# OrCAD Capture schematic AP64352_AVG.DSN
size D; title: 3.8V TO 40V INPUT, 3.5A LOW IQ SYNCHRONOUS BUCK; rev: 1.0; note: DS41978 Rev. 5 - 2
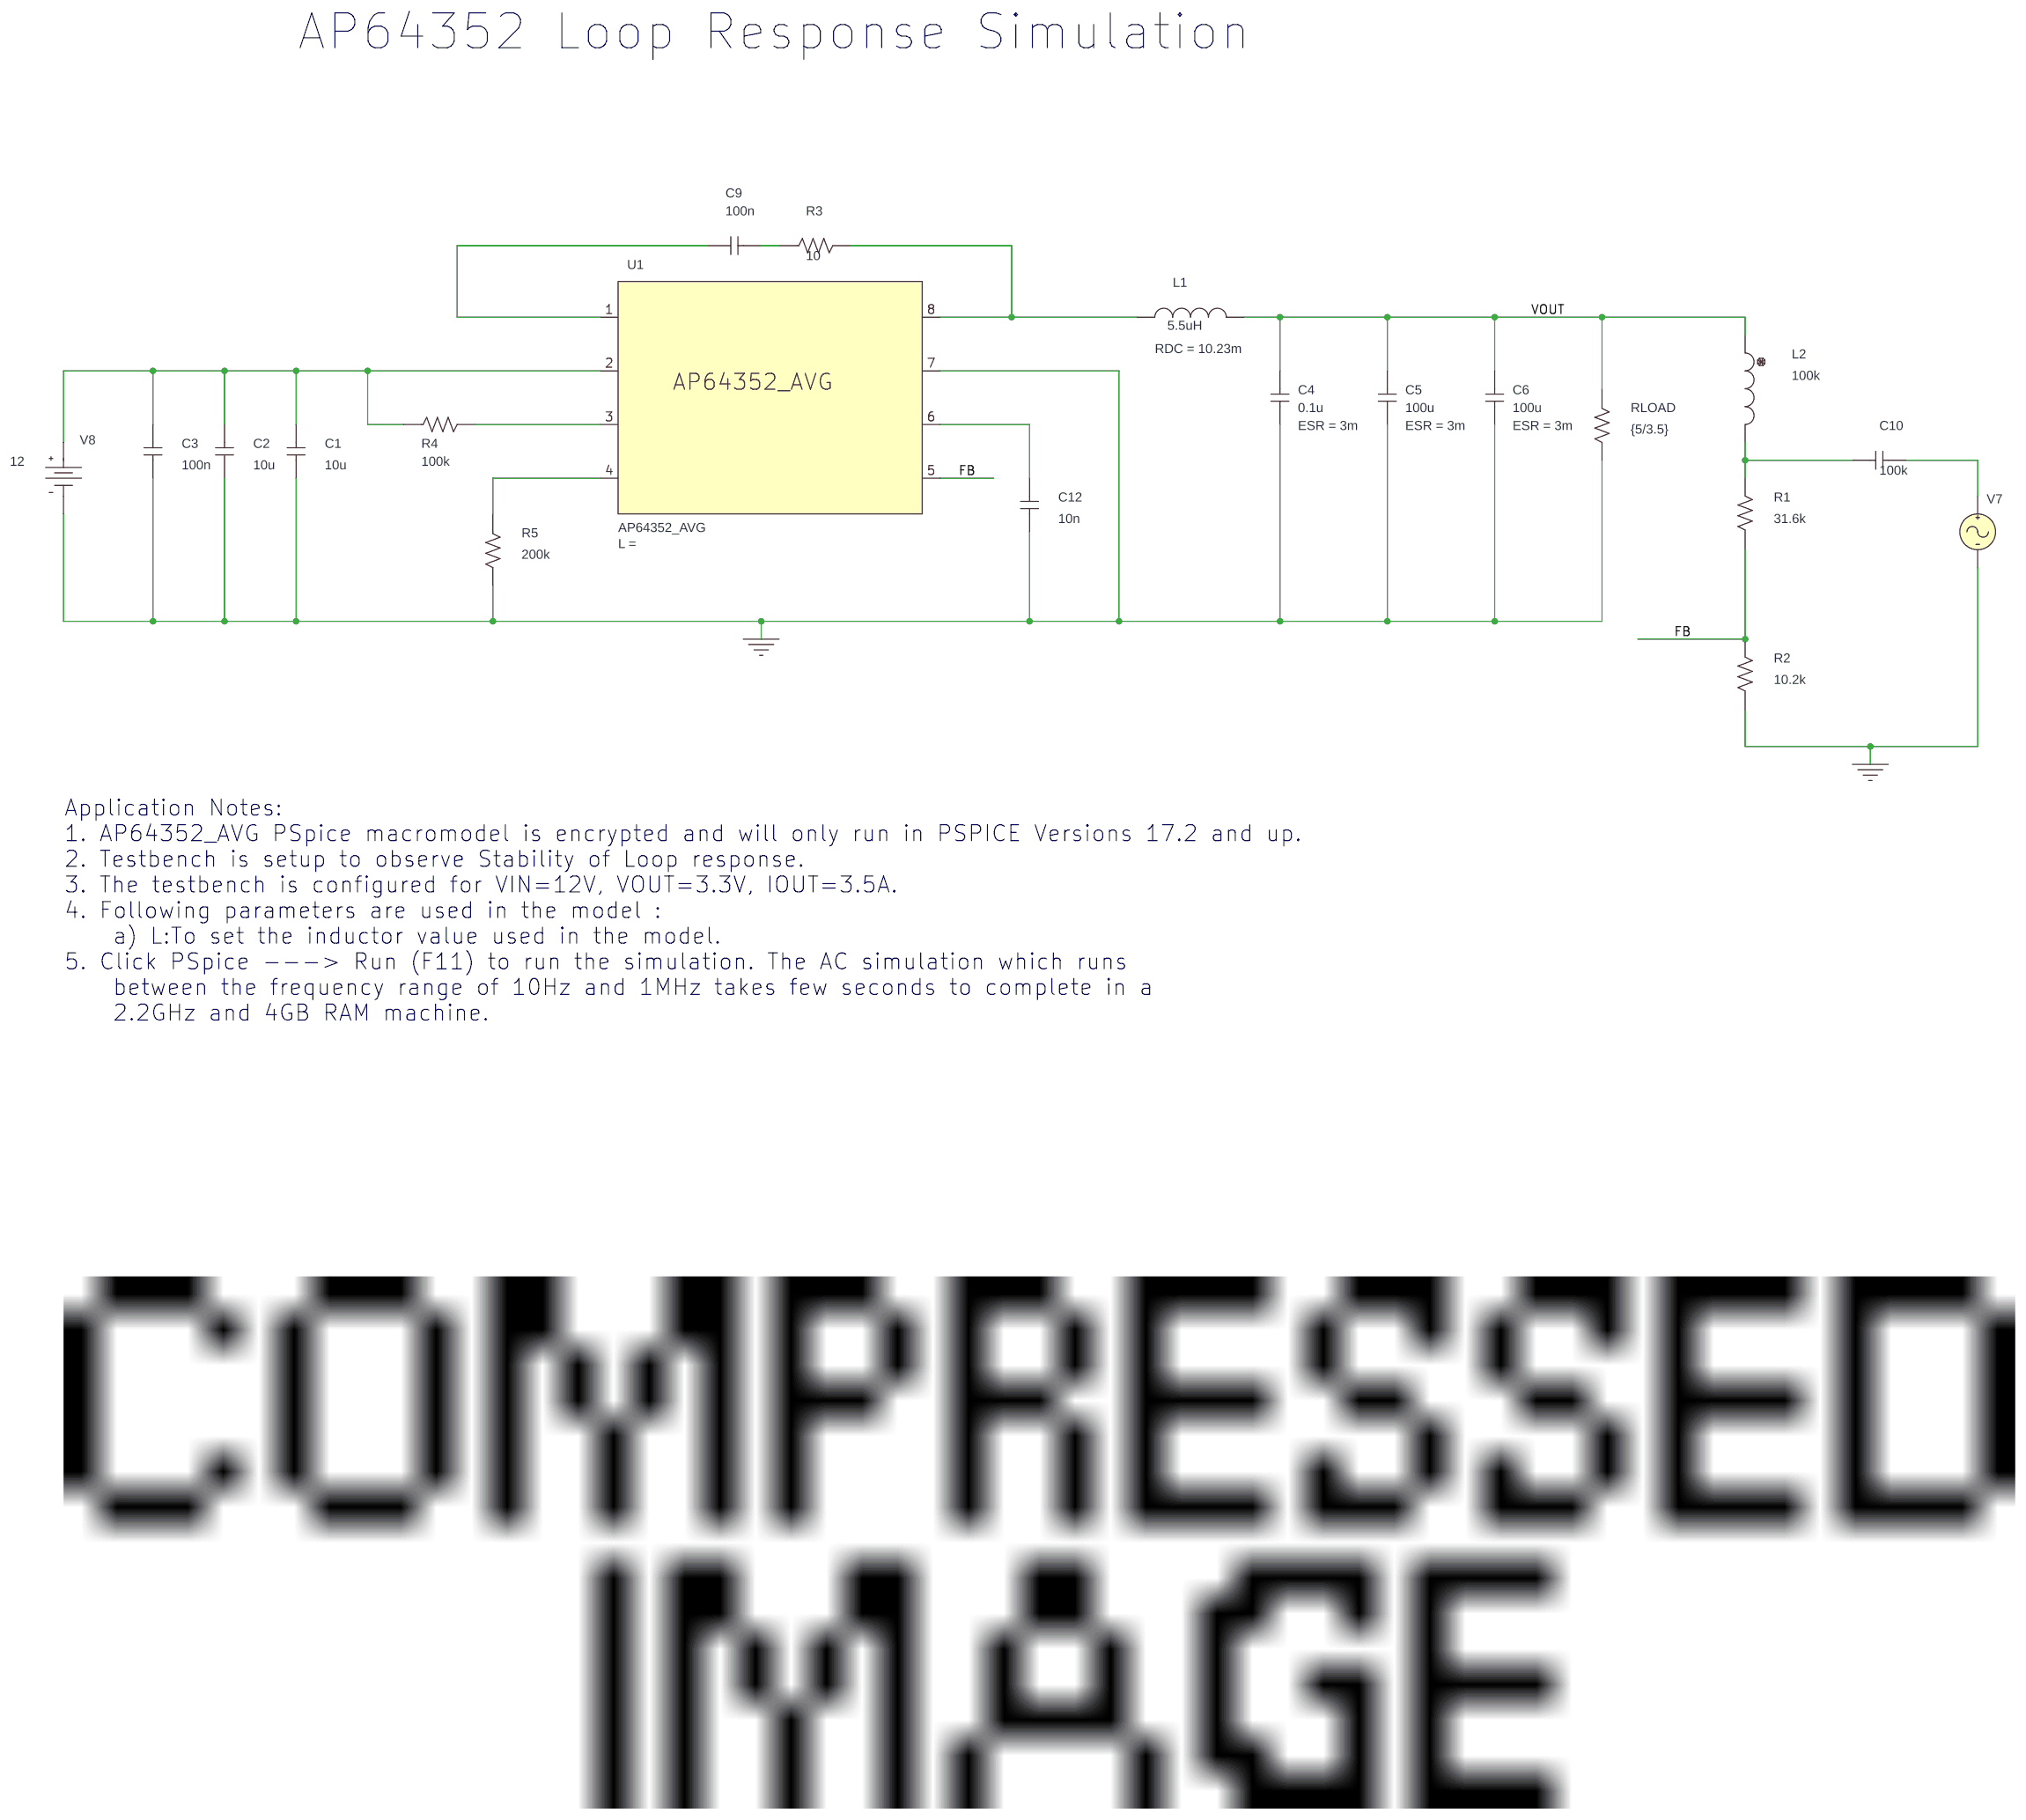
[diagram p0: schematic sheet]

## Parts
C1  10u  [cap196]
C2  10u  [cap196]
C3  100n  [cap196]
C4  0.1u  [RAD/CK05]
C5  100u  [RAD/CK05]
C6  100u  [RAD/CK05]
C9  100n  [cap196]
C10  100k  [cap196]
C12  10n  [cap196]
L1  5.5uH  [DISC/.350x.175/LS.200x.100/.034]
L2  100k  [DISC350x175LS200x100034]
R1  31.6k  [AXRC05]
R2  10.2k  [AXRC05]
R3  10  [AXRC05]
R4  100k  [AXRC05]
R5  200k  [AXRC05]
RLOAD  {5/3.5}  [AXRC05]
U1  AP64352_AVG
V7  VAC
V8  VDC

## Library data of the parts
C1-C3 C9 C10 C12 = C
C4-C6 = C: AppProp: InductiveSlave:;SRF:;PrevCap:220;PrevESL:; ESR: 3m
L1 = L_v2: AppProp: SRF:; RDC: 10.23m
L2 = L
R1-R5 RLOAD = R
U1 = AP64352_AVG
V7 = VAC
V8 = VDC: DC: 12

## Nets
0: C1.2 C2.2 C3.2 C4.2 C5.2 C6.2 C12.2 R2.1 R5.2 RLOAD.2 U1.7(GND) V7.2(-) V8.1(-)
FB: R1.1 R2.2 U1.5(FB)
VOUT: C4.1 C5.1 C6.1 L1.2 L2.1 RLOAD.1
N16065530: L1.1 R3.2 U1.8(SW)
N16065698: C10.1 L2.2 R1.2
N16065728: C10.2 V7.1(+)
N16066237: C12.1 U1.6(SS)
N16066498: C1.1 C2.1 C3.1 R4.1 U1.2(VIN) V8.0(+)
N16066808: C9.2 R3.1
N16066852: C9.1 U1.1(BST)
N16066923: R4.2 U1.3(EN)
N16067731: R5.1 U1.4(RT_CLK)

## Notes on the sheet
- AP64352 Loop Response Simulation
- Application Notes:
  1. AP64352_AVG PSpice macromodel is encrypted and will only run in PSPICE Versions 17.2 and up.
  2. Testbench is setup to observe Stability of Loop response.
  3. The testbench is configured for VIN=12V, VOUT=3.3V, IOUT=3.5A.
  4. Following parameters are used in the model :
      a) L:To set the inductor value used in the model.
  5. Click PSpice ---> Run (F11) to run the simulation. The AC simulation which runs
      between the frequency range of 10Hz and 1MHz takes few seconds to complete in a
      2.2GHz and 4GB RAM machine.
